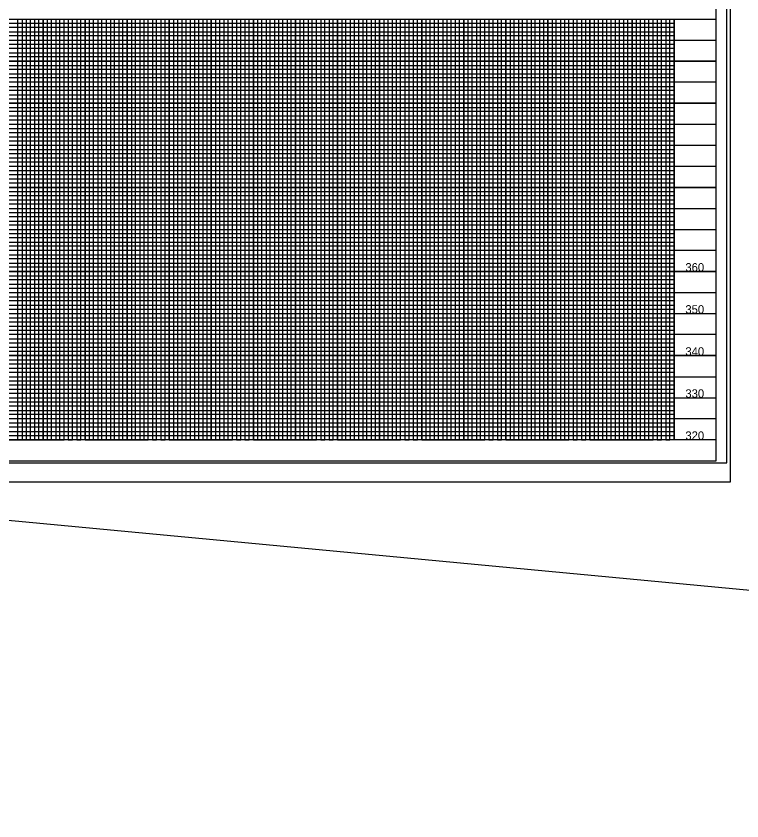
# Model space of a CAD drawing. Extents: x 571503 to 593215, y -77195 to -51828.
# Drawn here: x 588720 to 589583, y -54155 to -53198 of the extents above; entities that cross this region are included whole.
import ezdxf

# ---------------------------------------------------------------- set-up
doc = ezdxf.new("R2010")
doc.units = 0
for name, color, linetype in [('Exist Vertical Profile Vertical Axis Label', 7, 'Continuous'), ('Prop PFL Text', 7, 'Continuous'), ('Sheet Clip Boundary CELL', 7, 'Continuous'), ('Sheet DOT Grid CELL', 7, 'Continuous'), ('Sheet Plot Border Inside CELL', 7, 'Continuous'), ('Sheet Plot Border Outside CELL', 7, 'Continuous'), ('Sheet Profile CELL', 7, 'Continuous'), ('Sheet Profile Grid Major CELL', 7, 'Continuous'), ('Sheet Profile Grid Middle CELL', 7, 'Continuous'), ('Sheet Profile Grid Minor CELL', 7, 'Continuous')]:
    doc.layers.add(name, color=color, linetype=linetype)

msp = doc.modelspace()

# ---------------------------------------------------------------- linework, layer by layer
at = {"layer": 'Prop PFL Text'}
msp.add_line((571620.66, -52186.29), (592499.52, -54154.87), dxfattribs=at)
at = {"layer": 'Sheet Clip Boundary CELL'}
msp.add_lwpolyline([(588102.46, -53201.95), (589502.46, -53201.95), (589502.46, -53701.95), (588102.46, -53701.95)], close=True, dxfattribs=at)
at = {"layer": 'Sheet DOT Grid CELL'}
for p, q in [((588052.46, -53201.95), (589552.35, -53201.95)), ((588752.46, -53701.95), (588752.46, -53201.95)), ((588752.46, -53201.95), (588752.46, -53701.95)), ((588802.46, -53701.95), (588802.46, -53201.95)), ((588802.46, -53201.95), (588802.46, -53701.95)), ((588852.46, -53701.95), (588852.46, -53201.95)), ((588852.46, -53201.95), (588852.46, -53701.95)), ((588902.46, -53701.95), (588902.46, -53201.95)), ((588902.46, -53201.95), (588902.46, -53701.95)), ((588952.46, -53701.95), (588952.46, -53201.95)), ((588952.46, -53201.95), (588952.46, -53701.95)), ((589002.46, -53701.95), (589002.46, -53201.95)), ((589002.46, -53201.95), (589002.46, -53701.95)), ((589052.46, -53701.95), (589052.46, -53201.95)), ((589052.46, -53201.95), (589052.46, -53701.95)), ((589102.46, -53701.95), (589102.46, -53201.95)), ((589102.46, -53201.95), (589102.46, -53701.95)), ((589152.46, -53701.95), (589152.46, -53201.95)), ((589152.46, -53201.95), (589152.46, -53701.95)), ((589202.46, -53701.95), (589202.46, -53201.95)), ((589202.46, -53201.95), (589202.46, -53701.95)), ((589252.46, -53701.95), (589252.46, -53201.95)), ((589252.46, -53201.95), (589252.46, -53701.95)), ((589302.46, -53701.95), (589302.46, -53201.95)), ((589302.46, -53201.95), (589302.46, -53701.95)), ((589352.46, -53701.95), (589352.46, -53201.95)), ((589352.46, -53201.95), (589352.46, -53701.95)), ((589402.46, -53701.95), (589402.46, -53201.95)), ((589402.46, -53201.95), (589402.46, -53701.95)), ((589452.46, -53701.95), (589452.46, -53201.95)), ((589452.46, -53201.95), (589452.46, -53701.95)), ((589502.46, -53701.95), (589502.46, -53201.95)), ((589502.46, -53201.95), (589502.46, -53701.95)), ((588052.46, -53251.95), (589552.46, -53251.95)), ((588052.46, -53251.95), (589552.35, -53251.95)), ((588052.46, -53301.95), (589552.46, -53301.95)), ((588052.46, -53301.95), (589552.35, -53301.95)), ((588052.46, -53351.95), (589552.46, -53351.95)), ((588052.46, -53351.95), (589552.35, -53351.95)), ((588052.46, -53401.95), (589552.46, -53401.95)), ((588052.46, -53401.95), (589552.35, -53401.95)), ((588052.46, -53451.95), (589552.46, -53451.95)), ((588052.46, -53451.95), (589552.35, -53451.95)), ((588052.46, -53501.95), (589552.46, -53501.95)), ((588052.46, -53501.95), (589552.35, -53501.95)), ((588052.46, -53551.95), (589552.46, -53551.95)), ((588052.46, -53551.95), (589552.35, -53551.95)), ((588052.46, -53601.95), (589552.46, -53601.95)), ((588052.46, -53601.95), (589552.35, -53601.95)), ((588052.46, -53651.95), (589552.46, -53651.95)), ((588052.46, -53651.95), (589552.35, -53651.95))]:
    msp.add_line(p, q, dxfattribs=at)
at = {"layer": 'Sheet Plot Border Inside CELL'}
msp.add_lwpolyline([(587898.46, -53729.5), (589564.96, -53729.5), (589564.96, -52674.4), (587898.46, -52674.4)], close=True, dxfattribs=at)
at = {"layer": 'Sheet Plot Border Outside CELL'}
msp.add_lwpolyline([(587885.46, -53751.95), (589569.46, -53751.95), (589569.46, -52651.95), (587885.46, -52651.95)], close=True, dxfattribs=at)
at = {"layer": 'Sheet Profile CELL'}
for p, q in [((588052.46, -53201.95), (589552.46, -53201.95)), ((589552.46, -53701.95), (588052.46, -53701.95)), ((588052.46, -53726.95), (589552.46, -53726.95)), ((587885.46, -53751.95), (589569.46, -53751.95))]:
    msp.add_line(p, q, dxfattribs=at)
msp.add_lwpolyline([(589552.46, -52676.95), (588052.46, -52676.95), (588052.46, -53726.95), (589552.46, -53726.95)], close=True, dxfattribs=at)
at = {"layer": 'Sheet Profile Grid Major CELL'}
for p, q in [((588752.46, -53201.95), (588802.46, -53201.95)), ((588852.46, -53201.95), (588902.46, -53201.95)), ((588952.46, -53201.95), (589002.46, -53201.95)), ((589052.46, -53201.95), (589102.46, -53201.95)), ((589152.46, -53201.95), (589202.46, -53201.95)), ((589252.46, -53201.95), (589302.46, -53201.95)), ((589352.46, -53201.95), (589402.46, -53201.95)), ((589452.46, -53201.95), (589502.46, -53201.95)), ((589452.46, -53701.95), (589452.46, -53701.95))]:
    msp.add_line(p, q, dxfattribs=at)
for points in [[(588702.46, -53701.95), (588752.46, -53701.95), (588752.46, -53201.95), (588802.46, -53201.95), (588802.46, -53701.95), (588852.46, -53701.95), (588852.46, -53201.95), (588902.46, -53201.95), (588902.46, -53701.95), (588952.46, -53701.95), (588952.46, -53201.95), (589002.46, -53201.95), (589002.46, -53701.95), (589052.46, -53701.95), (589052.46, -53201.95), (589102.46, -53201.95), (589102.46, -53701.95), (589152.46, -53701.95), (589152.46, -53201.95), (589202.46, -53201.95), (589202.46, -53701.95), (589252.46, -53701.95), (589252.46, -53201.95), (589302.46, -53201.95), (589302.46, -53701.95), (589352.46, -53701.95), (589352.46, -53201.95), (589402.46, -53201.95), (589402.46, -53701.95), (589452.46, -53701.95), (589452.46, -53701.95), (589452.46, -53201.95), (589502.46, -53201.95), (589502.46, -53701.95)], [(589552.46, -53251.95), (588052.46, -53251.95)], [(589552.46, -53301.95), (588052.46, -53301.95), (588052.46, -53351.95), (589552.46, -53351.95)], [(589552.46, -53401.95), (588052.46, -53401.95), (588052.46, -53451.95), (589552.46, -53451.95)], [(589552.46, -53501.95), (588052.46, -53501.95), (588052.46, -53551.95), (589552.46, -53551.95)], [(589552.46, -53601.95), (588052.46, -53601.95), (588052.46, -53601.95), (588052.46, -53651.95), (589552.46, -53651.95)], [(589552.46, -53701.95), (588052.46, -53701.95)]]:
    msp.add_lwpolyline(points, dxfattribs=at)
at = {"layer": 'Sheet Profile Grid Middle CELL'}
for points in [[(588677.46, -53201.95), (588727.46, -53201.95), (588727.46, -53701.95), (588777.46, -53701.95), (588777.46, -53201.95), (588827.46, -53201.95), (588827.46, -53701.95), (588877.46, -53701.95), (588877.46, -53201.95), (588927.46, -53201.95), (588927.46, -53701.95), (588977.46, -53701.95), (588977.46, -53201.95), (589027.46, -53201.95), (589027.46, -53701.95), (589077.46, -53701.95), (589077.46, -53201.95), (589127.46, -53201.95), (589127.46, -53701.95), (589177.46, -53701.95), (589177.46, -53201.95), (589227.46, -53201.95), (589227.46, -53701.95), (589277.46, -53701.95), (589277.46, -53201.95), (589327.46, -53201.95), (589327.46, -53701.95), (589377.46, -53701.95), (589377.46, -53201.95), (589427.46, -53201.95), (589427.46, -53701.95), (589477.46, -53701.95), (589477.46, -53201.95)], [(588052.46, -53226.95), (589552.46, -53226.95)], [(589552.46, -53276.95), (588052.46, -53276.95), (588052.46, -53326.95), (589552.46, -53326.95)], [(589552.46, -53376.95), (588052.46, -53376.95), (588052.46, -53426.95), (589552.46, -53426.95)], [(589552.46, -53476.95), (588052.46, -53476.95), (588052.46, -53526.95), (589552.46, -53526.95)], [(589552.46, -53576.95), (588052.46, -53576.95), (588052.46, -53626.95), (589552.46, -53626.95)], [(589552.46, -53676.95), (588052.46, -53676.95)]]:
    msp.add_lwpolyline(points, dxfattribs=at)
at = {"layer": 'Sheet Profile Grid Minor CELL'}
for p, q in [((588102.46, -53206.95), (589502.46, -53206.95)), ((589502.46, -53211.95), (588102.46, -53211.95)), ((588102.46, -53216.95), (589502.46, -53216.95)), ((589502.46, -53221.95), (588102.46, -53221.95)), ((588102.46, -53231.95), (589502.46, -53231.95)), ((589502.46, -53236.95), (588102.46, -53236.95)), ((588102.46, -53241.95), (589502.46, -53241.95)), ((589502.46, -53246.95), (588102.46, -53246.95)), ((588102.46, -53256.95), (589502.46, -53256.95)), ((589502.46, -53261.95), (588102.46, -53261.95)), ((588102.46, -53266.95), (589502.46, -53266.95)), ((589502.46, -53271.95), (588102.46, -53271.95)), ((588102.46, -53281.95), (589502.46, -53281.95)), ((589502.46, -53286.95), (588102.46, -53286.95)), ((588102.46, -53291.95), (589502.46, -53291.95)), ((589502.46, -53296.95), (588102.46, -53296.95)), ((588102.46, -53306.95), (589502.46, -53306.95)), ((589502.46, -53311.95), (588102.46, -53311.95)), ((588102.46, -53316.95), (589502.46, -53316.95)), ((589502.46, -53321.95), (588102.46, -53321.95)), ((588102.46, -53331.95), (589502.46, -53331.95)), ((589502.46, -53336.95), (588102.46, -53336.95)), ((588102.46, -53341.95), (589502.46, -53341.95)), ((589502.46, -53346.95), (588102.46, -53346.95)), ((588102.46, -53356.95), (589502.46, -53356.95)), ((589502.46, -53361.95), (588102.46, -53361.95)), ((588102.46, -53366.95), (589502.46, -53366.95)), ((589502.46, -53371.95), (588102.46, -53371.95)), ((588102.46, -53381.95), (589502.46, -53381.95)), ((589502.46, -53386.95), (588102.46, -53386.95)), ((588102.46, -53391.95), (589502.46, -53391.95)), ((589502.46, -53396.95), (588102.46, -53396.8)), ((588102.46, -53406.95), (589502.46, -53406.95)), ((589502.46, -53411.95), (588102.46, -53411.95)), ((588102.46, -53416.95), (589502.46, -53416.95)), ((589502.46, -53421.95), (588102.46, -53421.95)), ((588102.46, -53431.95), (589502.46, -53431.95)), ((589502.46, -53436.95), (588102.46, -53436.95)), ((588102.46, -53441.95), (589502.46, -53441.95)), ((589502.46, -53446.95), (588102.46, -53446.95)), ((588102.46, -53456.95), (589502.46, -53456.95)), ((589502.46, -53461.95), (588102.46, -53461.95)), ((588102.46, -53466.95), (589502.46, -53466.95)), ((589502.46, -53471.95), (588102.46, -53471.95)), ((588102.46, -53481.95), (589502.46, -53481.95)), ((589502.46, -53486.95), (588102.46, -53486.95)), ((588102.46, -53491.95), (589502.46, -53491.95)), ((589502.46, -53496.95), (588102.46, -53496.95)), ((588102.46, -53506.95), (589502.46, -53506.95)), ((589502.46, -53511.95), (588102.46, -53511.95)), ((588102.46, -53516.95), (589502.46, -53516.95)), ((589502.46, -53521.95), (588102.46, -53521.95)), ((588102.46, -53531.95), (589502.46, -53531.95)), ((589502.46, -53536.95), (588102.46, -53536.95)), ((588102.46, -53541.95), (589502.46, -53541.95)), ((589502.46, -53546.95), (588102.46, -53546.95)), ((588102.46, -53556.95), (589502.46, -53556.95)), ((589502.46, -53561.95), (588102.46, -53561.95)), ((588102.46, -53566.95), (589502.46, -53566.95)), ((589502.46, -53571.95), (588102.46, -53571.95)), ((588102.46, -53581.95), (589502.46, -53581.95)), ((589502.46, -53586.95), (588102.46, -53586.95)), ((588102.46, -53591.95), (589502.46, -53591.95)), ((589502.46, -53596.95), (588102.46, -53596.95)), ((588102.46, -53606.95), (589502.46, -53606.95)), ((589502.46, -53611.95), (588102.46, -53611.95)), ((588102.46, -53616.95), (589502.46, -53616.95)), ((589502.46, -53621.95), (588102.46, -53621.95)), ((588102.46, -53631.95), (589502.46, -53631.95)), ((589502.46, -53636.95), (588102.46, -53636.95)), ((588102.46, -53641.95), (589502.46, -53641.95)), ((589502.46, -53646.95), (588102.46, -53646.95)), ((588102.46, -53656.95), (589502.46, -53656.95)), ((589502.46, -53661.95), (588102.46, -53661.95)), ((588102.46, -53666.95), (589502.46, -53666.95)), ((589502.46, -53671.95), (588102.46, -53671.95)), ((588102.46, -53681.95), (589502.46, -53681.95)), ((589502.46, -53686.95), (588102.46, -53686.95)), ((588102.46, -53691.95), (589502.46, -53691.95)), ((588102.46, -53696.95), (589502.46, -53696.95)), ((589502.46, -53696.95), (589502.46, -53696.95))]:
    msp.add_line(p, q, dxfattribs=at)
for points in [[(588717.46, -53701.95), (588722.46, -53701.95), (588722.46, -53201.95), (588732.46, -53201.95), (588732.46, -53701.95), (588737.46, -53701.95), (588737.46, -53201.95), (588742.46, -53201.95), (588742.46, -53701.95), (588747.46, -53701.95), (588747.46, -53201.95), (588757.46, -53201.95), (588757.46, -53701.95), (588757.46, -53701.95), (588762.46, -53701.95), (588762.46, -53201.95), (588767.46, -53201.95), (588767.46, -53701.95), (588772.46, -53701.95), (588772.46, -53201.95), (588782.46, -53201.95), (588782.46, -53701.95), (588787.46, -53701.95), (588787.46, -53201.95), (588792.46, -53201.95), (588792.46, -53701.95), (588797.46, -53701.95), (588797.46, -53201.95), (588807.46, -53201.95), (588807.46, -53701.95), (588812.46, -53701.95), (588812.46, -53201.95), (588817.46, -53201.95), (588817.46, -53701.95), (588822.46, -53701.95), (588822.46, -53201.95), (588832.46, -53201.95), (588832.46, -53701.95), (588837.46, -53701.95), (588837.46, -53201.95), (588842.46, -53201.95), (588842.46, -53701.95), (588847.46, -53701.95), (588847.46, -53201.95), (588857.46, -53201.95), (588857.46, -53701.95), (588862.46, -53701.95), (588862.46, -53201.95), (588867.46, -53201.95), (588867.46, -53701.95), (588872.46, -53701.95), (588872.46, -53201.95), (588882.46, -53201.95), (588882.46, -53701.95), (588887.46, -53701.95), (588887.46, -53201.95), (588892.46, -53201.95), (588892.46, -53701.95), (588897.46, -53701.95), (588897.46, -53201.95), (588907.46, -53201.95), (588907.46, -53701.95), (588912.16, -53701.4), (588912.46, -53701.95), (588912.46, -53201.95), (588917.46, -53201.95), (588917.46, -53701.95), (588922.46, -53701.95), (588922.46, -53201.95), (588932.46, -53201.95), (588932.46, -53701.95), (588937.46, -53701.95)], [(588937.46, -53701.95), (588937.46, -53201.95), (588942.46, -53201.95), (588942.46, -53701.95), (588947.46, -53701.95), (588947.46, -53201.95), (588957.46, -53201.95), (588957.46, -53701.95), (588962.46, -53701.95), (588962.46, -53201.95), (588967.46, -53201.95), (588967.46, -53701.95), (588972.46, -53701.95), (588972.46, -53201.95), (588982.46, -53201.95), (588982.46, -53701.95), (588987.46, -53701.95), (588987.46, -53201.95), (588992.46, -53201.95), (588992.46, -53701.95), (588997.46, -53701.95), (588997.46, -53201.95), (589007.46, -53201.95), (589007.46, -53701.95), (589012.46, -53701.95), (589012.46, -53201.95), (589017.46, -53201.95), (589017.46, -53701.95), (589022.46, -53701.95), (589022.46, -53201.95), (589032.46, -53201.95), (589032.46, -53701.95), (589037.46, -53701.95), (589037.46, -53201.95), (589042.46, -53201.95), (589042.46, -53701.95), (589047.46, -53701.95), (589047.46, -53201.95), (589057.46, -53201.95), (589057.46, -53701.95), (589062.46, -53701.95), (589062.46, -53201.95), (589067.46, -53201.95), (589067.46, -53701.95), (589072.46, -53701.95), (589072.46, -53201.95), (589082.46, -53201.95), (589082.46, -53701.95), (589087.46, -53701.95), (589087.46, -53201.95), (589092.46, -53201.95), (589092.46, -53701.95), (589097.46, -53701.95), (589097.46, -53201.95), (589107.46, -53201.95), (589107.46, -53701.95), (589112.46, -53701.95), (589112.46, -53201.95), (589117.46, -53201.95), (589117.46, -53701.95), (589122.46, -53701.95), (589122.46, -53201.95), (589132.46, -53201.95), (589132.46, -53701.95), (589137.46, -53701.95), (589137.46, -53201.95), (589142.46, -53201.95), (589142.46, -53701.95), (589147.46, -53701.95), (589147.46, -53201.95), (589157.46, -53201.95), (589157.46, -53701.95), (589162.46, -53701.95), (589162.46, -53201.95), (589167.46, -53201.95), (589167.46, -53701.95), (589172.46, -53701.95), (589172.46, -53201.95), (589182.46, -53201.95), (589182.46, -53701.95), (589187.46, -53701.95), (589187.46, -53201.95), (589192.46, -53201.95), (589192.46, -53701.95), (589197.46, -53701.95), (589197.46, -53201.95), (589207.46, -53201.95), (589207.46, -53701.95), (589212.46, -53701.95), (589212.46, -53201.95), (589217.46, -53201.95), (589217.46, -53701.95), (589222.46, -53701.95), (589222.46, -53201.95), (589232.46, -53201.95), (589232.46, -53701.95), (589237.46, -53701.95), (589237.46, -53201.95), (589242.46, -53201.95), (589242.46, -53701.95)], [(589242.46, -53701.95), (589247.46, -53701.95), (589247.46, -53201.95), (589257.46, -53201.95), (589257.46, -53701.95), (589262.46, -53701.95), (589262.46, -53201.95), (589267.46, -53201.95), (589267.46, -53701.95), (589272.46, -53701.95), (589272.46, -53201.95), (589282.46, -53201.95), (589282.46, -53701.95), (589287.46, -53701.95), (589287.46, -53201.95), (589292.46, -53201.95), (589292.46, -53701.95), (589297.46, -53701.95), (589297.46, -53201.95), (589307.46, -53201.95), (589307.46, -53701.95), (589312.46, -53701.95), (589312.46, -53201.95), (589317.46, -53201.95), (589317.46, -53701.95), (589322.46, -53701.95), (589322.46, -53201.95), (589332.46, -53201.95), (589332.46, -53701.95), (589337.46, -53701.95), (589337.46, -53201.95), (589342.46, -53201.95), (589342.46, -53701.95), (589347.46, -53701.95), (589347.46, -53201.95), (589357.46, -53201.95), (589357.46, -53701.95), (589362.46, -53701.95), (589362.46, -53201.95), (589367.46, -53201.95), (589367.46, -53701.95), (589372.46, -53701.95), (589372.46, -53201.95), (589382.46, -53201.95), (589382.46, -53701.95), (589387.46, -53701.95), (589387.46, -53201.95), (589392.46, -53201.95), (589392.46, -53701.95), (589397.46, -53701.95), (589397.46, -53201.95), (589407.46, -53201.95), (589407.46, -53701.95), (589412.46, -53701.95), (589412.46, -53201.95), (589417.46, -53201.95), (589417.46, -53701.95), (589422.46, -53701.95), (589422.46, -53201.95), (589432.46, -53201.95), (589432.46, -53701.95), (589437.46, -53701.95), (589437.46, -53201.95), (589442.46, -53201.95), (589442.46, -53701.95), (589447.46, -53701.95), (589447.46, -53201.95), (589457.46, -53201.95), (589457.46, -53701.95), (589462.46, -53701.95), (589462.46, -53201.95), (589467.46, -53201.95), (589467.46, -53701.95), (589472.46, -53701.95), (589472.46, -53201.95), (589482.46, -53201.95), (589482.46, -53701.95), (589487.46, -53701.95), (589487.46, -53201.95), (589492.46, -53201.95), (589492.46, -53701.95), (589497.46, -53701.95), (589497.46, -53201.95), (589502.46, -53201.95)]]:
    msp.add_lwpolyline(points, dxfattribs=at)

# ---------------------------------------------------------------- texts
at = {"layer": 'Exist Vertical Profile Vertical Axis Label'}
for s, p in [('360', (589515.89, -53501.95)), ('350', (589515.89, -53551.95)), ('340', (589515.89, -53601.95)), ('330', (589515.89, -53651.95)), ('320', (589515.89, -53701.95))]:
    msp.add_text(s, height=10, dxfattribs=at).set_placement(p)

doc.saveas('drawing.dxf')
